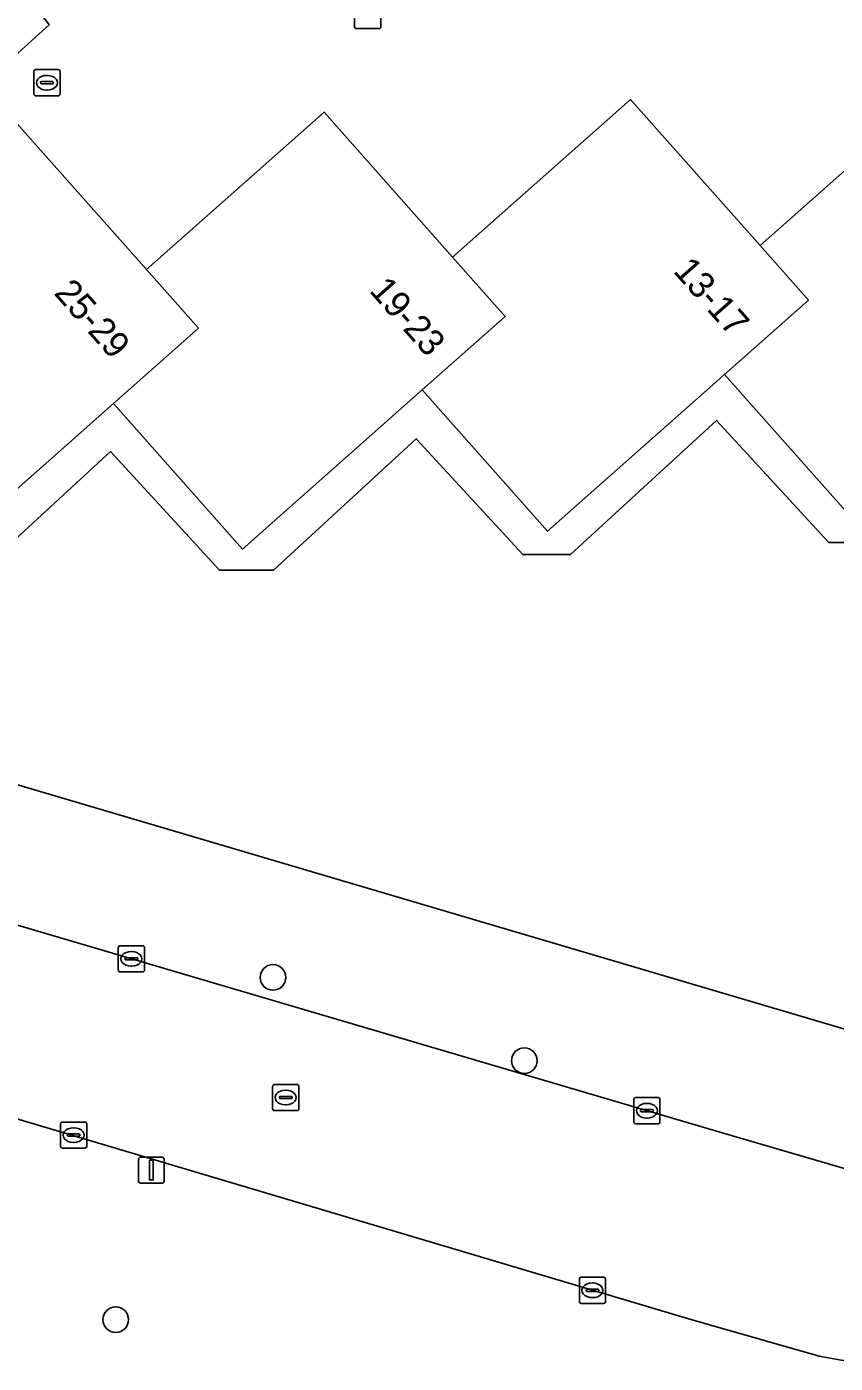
# Model space of a CAD drawing. Extents: x 160349 to 161355, y 381727 to 382854.
# Drawn here: x 160794 to 160824.9, y 381867.4 to 381918.5 of the extents above; entities that cross this region are included whole.
import ezdxf

# ---------------------------------------------------------------- set-up
doc = ezdxf.new("R2010")
doc.units = 0
for name, color, linetype in [('IMGEO_Berm_groen', 7, 'Continuous'), ('IMGEO_Boom', 7, 'Continuous'), ('IMGEO_Brandkraan', 7, 'Continuous'), ('IMGEO_Groenvoorziening', 7, 'Continuous'), ('IMGEO_Kolk', 7, 'Continuous'), ('IMGEO_Lichtmast', 7, 'Continuous'), ('IMGEO_Pand', 7, 'Continuous'), ('IMGEO_Pand_nummerreeks', 7, 'Continuous'), ('IMGEO_Rijbaan_lokaal_open', 7, 'Continuous'), ('IMGEO_Rioolput', 7, 'Continuous'), ('IMGEO_Voetpad_halfverhard', 7, 'Continuous'), ('IMGEO_Voetpad_open', 7, 'Continuous')]:
    doc.layers.add(name, color=color, linetype=linetype)

msp = doc.modelspace()

# ---------------------------------------------------------------- linework, layer by layer
at = {"layer": 'IMGEO_Berm_groen'}
msp.add_lwpolyline([(160824.304, 381867.688), (160819.275, 381869.125), (160815.643, 381870.203), (160710.934, 381901.384), (160677.174, 381911.473), (160673.041, 381902.206), (160697.175, 381891.554), (160719.115, 381882.137)], dxfattribs=at)
msp.add_arc((160826.897, 381879.851), 12.436, 257.9663, 319.7044, dxfattribs=at)
at = {"layer": 'IMGEO_Boom'}
for centre in [(160803.44, 381882.157), (160813.042, 381878.975), (160797.437, 381869.081)]:
    msp.add_circle(centre, 0.489, dxfattribs=at)
at = {"layer": 'IMGEO_Brandkraan'}
for p, q in [((160794.307, 381915.913), (160794.307, 381916.765)), ((160794.382, 381916.839), (160795.234, 381916.839)), ((160795.308, 381916.765), (160795.308, 381915.913)), ((160794.566, 381916.333), (160794.566, 381916.345)), ((160795.004, 381916.296), (160794.606, 381916.296)), ((160794.609, 381916.382), (160795.007, 381916.382)), ((160794.795, 381916.619), (160794.82, 381916.619)), ((160795.05, 381916.345), (160795.05, 381916.333)), ((160795.234, 381915.839), (160794.382, 381915.839)), ((160794.818, 381916.059), (160794.793, 381916.059))]:
    msp.add_line(p, q, dxfattribs=at)
for points in [[(160794.307, 381915.913), (160794.307, 381916.765)], [(160794.382, 381916.839), (160795.234, 381916.839)], [(160795.308, 381916.765), (160795.308, 381915.913)], [(160795.234, 381915.839), (160794.382, 381915.839)]]:
    msp.add_lwpolyline(points, dxfattribs=at)
for centre, radius, start, end in [((160794.384, 381916.763), 0.0765, 91.552, 178.448), ((160794.384, 381916.763), 0.0765, 91.552, 178.448), ((160795.232, 381916.763), 0.0765, 1.552, 88.448), ((160795.232, 381916.763), 0.0765, 1.552, 88.448), ((160794.606, 381916.342), 0.0403, 85.8775, 175.7526), ((160794.603, 381916.332), 0.0366, 178.938, 274.7102), ((160795.007, 381916.339), 0.043, 264.8664, 352.4533), ((160795.011, 381916.344), 0.0386, 1.7309, 96.639), ((160794.384, 381915.915), 0.0765, 181.552, 268.448), ((160794.384, 381915.915), 0.0765, 181.552, 268.448), ((160795.232, 381915.915), 0.0765, 271.552, 358.448), ((160795.232, 381915.915), 0.0765, 271.552, 358.448)]:
    msp.add_arc(centre, radius, start, end, dxfattribs=at)
for centre, major_axis, ratio, start_param, end_param in [((160794.794, 381916.339), (-0.387, 0.002), 0.722429, 4.712389, 7.853982), ((160794.819, 381916.339), (-0.39, 0.002), 0.717154, 1.570796, 4.712389)]:
    msp.add_ellipse(centre, major_axis=major_axis, ratio=ratio, start_param=start_param, end_param=end_param, dxfattribs=at)
at = {"layer": 'IMGEO_Groenvoorziening'}
for points in [[(160792.633, 381916.513), (160794.892, 381918.548), (160790.477, 381924.479), (160794.37, 381927.389), (160789.06, 381934.483)], [(160773.845, 381895.369), (160826.057, 381879.947), (160836.265, 381891.816), (160848.899, 381907.299), (160848.175, 381908.11), (160838.505, 381899.482), (160838.387, 381899.373), (160836.448, 381899.369), (160836.345, 381899.482), (160832.232, 381903.953), (160826.807, 381898.962), (160826.597, 381898.769), (160824.673, 381898.769), (160824.495, 381898.962), (160820.379, 381903.436), (160814.808, 381898.312), (160812.983, 381898.312), (160808.912, 381902.737), (160803.458, 381897.72), (160801.4, 381897.72), (160797.233, 381902.25), (160791.795, 381897.247)]]:
    msp.add_lwpolyline(points, dxfattribs=at)
at = {"layer": 'IMGEO_Kolk'}
for p, q in [((160806.56, 381918.479), (160806.56, 381919.331)), ((160807.561, 381919.331), (160807.561, 381918.479)), ((160807.487, 381918.405), (160806.635, 381918.405)), ((160797.535, 381882.441), (160797.535, 381883.293)), ((160797.61, 381883.367), (160798.462, 381883.367)), ((160798.023, 381883.147), (160798.048, 381883.147)), ((160798.536, 381883.293), (160798.536, 381882.441)), ((160797.794, 381882.861), (160797.794, 381882.873)), ((160798.232, 381882.824), (160797.834, 381882.824)), ((160797.837, 381882.91), (160798.235, 381882.91)), ((160798.046, 381882.587), (160798.021, 381882.587)), ((160798.278, 381882.873), (160798.278, 381882.861)), ((160798.462, 381882.367), (160797.61, 381882.367)), ((160817.219, 381876.638), (160817.219, 381877.49)), ((160817.294, 381877.564), (160818.146, 381877.564)), ((160818.22, 381877.49), (160818.22, 381876.638)), ((160817.478, 381877.058), (160817.478, 381877.07)), ((160817.916, 381877.021), (160817.518, 381877.021)), ((160817.521, 381877.107), (160817.919, 381877.107)), ((160817.707, 381877.344), (160817.732, 381877.344)), ((160817.962, 381877.07), (160817.962, 381877.058)), ((160795.329, 381875.706), (160795.329, 381876.558)), ((160795.404, 381876.632), (160796.256, 381876.632)), ((160795.817, 381876.412), (160795.842, 381876.412)), ((160796.33, 381876.558), (160796.33, 381875.706)), ((160818.146, 381876.564), (160817.294, 381876.564)), ((160817.73, 381876.784), (160817.705, 381876.784)), ((160795.588, 381876.126), (160795.588, 381876.138)), ((160796.026, 381876.089), (160795.628, 381876.089)), ((160795.631, 381876.175), (160796.029, 381876.175)), ((160796.072, 381876.138), (160796.072, 381876.126)), ((160796.256, 381875.632), (160795.404, 381875.632)), ((160795.84, 381875.852), (160795.815, 381875.852)), ((160815.142, 381869.776), (160815.142, 381870.628)), ((160815.217, 381870.702), (160816.069, 381870.702)), ((160815.63, 381870.482), (160815.655, 381870.482)), ((160816.143, 381870.628), (160816.143, 381869.776)), ((160815.401, 381870.196), (160815.401, 381870.208)), ((160815.839, 381870.159), (160815.441, 381870.159)), ((160815.444, 381870.245), (160815.842, 381870.245)), ((160815.653, 381869.922), (160815.628, 381869.922)), ((160815.885, 381870.208), (160815.885, 381870.196)), ((160816.069, 381869.702), (160815.217, 381869.702))]:
    msp.add_line(p, q, dxfattribs=at)
for points in [[(160806.56, 381918.479), (160806.56, 381919.331)], [(160807.561, 381919.331), (160807.561, 381918.479)], [(160807.487, 381918.405), (160806.635, 381918.405)], [(160797.535, 381882.441), (160797.535, 381883.293)], [(160797.61, 381883.367), (160798.462, 381883.367)], [(160798.536, 381883.293), (160798.536, 381882.441)], [(160798.462, 381882.367), (160797.61, 381882.367)], [(160817.219, 381876.638), (160817.219, 381877.49)], [(160817.294, 381877.564), (160818.146, 381877.564)], [(160818.22, 381877.49), (160818.22, 381876.638)], [(160795.329, 381875.706), (160795.329, 381876.558)], [(160795.404, 381876.632), (160796.256, 381876.632)], [(160796.33, 381876.558), (160796.33, 381875.706)], [(160818.146, 381876.564), (160817.294, 381876.564)], [(160796.256, 381875.632), (160795.404, 381875.632)], [(160815.142, 381869.776), (160815.142, 381870.628)], [(160815.217, 381870.702), (160816.069, 381870.702)], [(160816.143, 381870.628), (160816.143, 381869.776)], [(160816.069, 381869.702), (160815.217, 381869.702)]]:
    msp.add_lwpolyline(points, dxfattribs=at)
for centre, radius, start, end in [((160806.637, 381918.481), 0.0765, 181.552, 268.448), ((160806.637, 381918.481), 0.0765, 181.552, 268.448), ((160807.485, 381918.481), 0.0765, 271.552, 358.448), ((160807.485, 381918.481), 0.0765, 271.552, 358.448), ((160797.612, 381883.291), 0.0765, 91.552, 178.448), ((160797.612, 381883.291), 0.0765, 91.552, 178.448), ((160798.46, 381883.291), 0.0765, 1.552, 88.448), ((160798.46, 381883.291), 0.0765, 1.552, 88.448), ((160797.834, 381882.87), 0.0403, 85.8775, 175.7526), ((160797.831, 381882.86), 0.0366, 178.938, 274.7102), ((160798.235, 381882.867), 0.043, 264.8664, 352.4533), ((160798.239, 381882.872), 0.0386, 1.7309, 96.639), ((160797.612, 381882.443), 0.0765, 181.552, 268.448), ((160797.612, 381882.443), 0.0765, 181.552, 268.448), ((160798.46, 381882.443), 0.0765, 271.552, 358.448), ((160798.46, 381882.443), 0.0765, 271.552, 358.448), ((160817.296, 381877.488), 0.0765, 91.552, 178.448), ((160817.296, 381877.488), 0.0765, 91.552, 178.448), ((160818.144, 381877.488), 0.0765, 1.552, 88.448), ((160818.144, 381877.488), 0.0765, 1.552, 88.448), ((160817.518, 381877.067), 0.0403, 85.8775, 175.7526), ((160817.515, 381877.057), 0.0366, 178.938, 274.7102), ((160817.919, 381877.064), 0.043, 264.8664, 352.4533), ((160817.923, 381877.069), 0.0386, 1.7309, 96.639), ((160795.406, 381876.556), 0.0765, 91.552, 178.448), ((160795.406, 381876.556), 0.0765, 91.552, 178.448), ((160796.254, 381876.556), 0.0765, 1.552, 88.448), ((160796.254, 381876.556), 0.0765, 1.552, 88.448), ((160817.296, 381876.64), 0.0765, 181.552, 268.448), ((160817.296, 381876.64), 0.0765, 181.552, 268.448), ((160818.144, 381876.64), 0.0765, 271.552, 358.448), ((160818.144, 381876.64), 0.0765, 271.552, 358.448), ((160795.628, 381876.135), 0.0403, 85.8775, 175.7526), ((160795.625, 381876.125), 0.0366, 178.938, 274.7102), ((160796.029, 381876.132), 0.043, 264.8664, 352.4533), ((160796.033, 381876.137), 0.0386, 1.7309, 96.639), ((160795.406, 381875.708), 0.0765, 181.552, 268.448), ((160795.406, 381875.708), 0.0765, 181.552, 268.448), ((160796.254, 381875.708), 0.0765, 271.552, 358.448), ((160796.254, 381875.708), 0.0765, 271.552, 358.448), ((160815.219, 381870.626), 0.0765, 91.552, 178.448), ((160815.219, 381870.626), 0.0765, 91.552, 178.448), ((160816.067, 381870.626), 0.0765, 1.552, 88.448), ((160816.067, 381870.626), 0.0765, 1.552, 88.448), ((160815.219, 381869.778), 0.0765, 181.552, 268.448), ((160815.219, 381869.778), 0.0765, 181.552, 268.448), ((160815.441, 381870.205), 0.0403, 85.8775, 175.7526), ((160815.438, 381870.195), 0.0366, 178.938, 274.7102), ((160815.842, 381870.202), 0.043, 264.8664, 352.4533), ((160815.846, 381870.207), 0.0386, 1.7309, 96.639), ((160816.067, 381869.778), 0.0765, 271.552, 358.448), ((160816.067, 381869.778), 0.0765, 271.552, 358.448)]:
    msp.add_arc(centre, radius, start, end, dxfattribs=at)
for centre, major_axis, ratio, start_param, end_param in [((160798.022, 381882.867), (-0.387, 0.002), 0.722429, 4.712389, 7.853982), ((160798.047, 381882.867), (-0.39, 0.002), 0.717154, 1.570796, 4.712389), ((160817.706, 381877.064), (-0.387, 0.002), 0.722429, 4.712389, 7.853982), ((160817.731, 381877.064), (-0.39, 0.002), 0.717154, 1.570796, 4.712389), ((160795.816, 381876.132), (-0.387, 0.002), 0.722429, 4.712389, 7.853982), ((160795.841, 381876.132), (-0.39, 0.002), 0.717154, 1.570796, 4.712389), ((160815.629, 381870.202), (-0.387, 0.002), 0.722429, 4.712389, 7.853982), ((160815.654, 381870.202), (-0.39, 0.002), 0.717154, 1.570796, 4.712389)]:
    msp.add_ellipse(centre, major_axis=major_axis, ratio=ratio, start_param=start_param, end_param=end_param, dxfattribs=at)
at = {"layer": 'IMGEO_Lichtmast'}
for p, q in [((160798.299, 381874.394), (160798.299, 381875.194)), ((160798.299, 381875.194), (160798.299, 381874.394)), ((160798.399, 381875.294), (160799.189, 381875.294)), ((160799.189, 381875.294), (160798.399, 381875.294)), ((160799.289, 381875.194), (160799.289, 381874.394)), ((160799.289, 381874.394), (160799.289, 381875.194)), ((160799.189, 381874.294), (160798.399, 381874.294)), ((160798.399, 381874.294), (160799.189, 381874.294))]:
    msp.add_line(p, q, dxfattribs=at)
msp.add_lwpolyline([(160798.719, 381875.169), (160798.869, 381875.169), (160798.869, 381874.419), (160798.719, 381874.419), (160798.719, 381875.169)], dxfattribs=at)
for centre, start, end in [((160798.399, 381875.194), 90, 180), ((160798.399, 381875.194), 90, 180), ((160799.189, 381875.194), 0, 90), ((160799.189, 381875.194), 360, 90), ((160798.399, 381874.394), 180, 270), ((160798.399, 381874.394), 180, 270), ((160799.189, 381874.394), 270, 0), ((160799.189, 381874.394), 270, 0)]:
    msp.add_arc(centre, 0.1, start, end, dxfattribs=at)
at = {"layer": 'IMGEO_Pand'}
for points in [[(160822.045, 381910.121), (160823.891, 381908.037), (160820.686, 381905.198), (160825.625, 381899.622), (160832.495, 381905.707), (160835.617, 381908.472), (160833.696, 381910.641), (160828.833, 381916.132)], [(160798.607, 381909.202), (160800.593, 381906.96), (160797.346, 381904.085), (160802.276, 381898.519), (160809.142, 381904.6), (160812.311, 381907.407), (160810.299, 381909.679), (160805.397, 381915.215)], [(160809.142, 381904.6), (160813.92, 381899.205), (160820.686, 381905.198), (160823.891, 381908.037), (160822.045, 381910.121), (160817.101, 381915.703), (160810.299, 381909.679), (160812.311, 381907.407)], [(160798.607, 381909.202), (160793.675, 381914.77), (160786.891, 381908.762), (160786.177, 381908.13), (160786.618, 381907.631), (160786.99, 381907.961), (160787.432, 381907.462), (160788.32, 381906.46), (160785.459, 381903.926), (160790.605, 381898.115), (160797.346, 381904.085), (160800.593, 381906.96)]]:
    msp.add_lwpolyline(points, close=True, dxfattribs=at)
at = {"layer": 'IMGEO_Rijbaan_lokaal_open'}
for points in [[(160703.301, 381910.962), (160691.804, 381914.329), (160679.993, 381917.834), (160677.174, 381911.473), (160710.934, 381901.384), (160815.643, 381870.203), (160819.275, 381869.125), (160824.304, 381867.688)], [(160826.955, 381874.36), (160820.691, 381876.187), (160744.941, 381898.519), (160740.094, 381899.948), (160729.348, 381903.194), (160724.219, 381904.806), (160713.383, 381907.976), (160703.301, 381910.962)]]:
    msp.add_lwpolyline(points, dxfattribs=at)
msp.add_arc((160826.897, 381879.851), 12.436, 257.9663, 319.7044, dxfattribs=at)
at = {"layer": 'IMGEO_Rioolput'}
for p, q in [((160803.429, 381877.142), (160803.429, 381877.994)), ((160803.504, 381878.068), (160804.356, 381878.068)), ((160804.43, 381877.994), (160804.43, 381877.142)), ((160803.688, 381877.562), (160803.688, 381877.574)), ((160804.126, 381877.525), (160803.728, 381877.525)), ((160803.731, 381877.611), (160804.129, 381877.611)), ((160803.917, 381877.848), (160803.942, 381877.848)), ((160804.172, 381877.574), (160804.172, 381877.562)), ((160804.356, 381877.068), (160803.504, 381877.068)), ((160803.94, 381877.288), (160803.915, 381877.288))]:
    msp.add_line(p, q, dxfattribs=at)
for points in [[(160803.429, 381877.142), (160803.429, 381877.994)], [(160803.504, 381878.068), (160804.356, 381878.068)], [(160804.43, 381877.994), (160804.43, 381877.142)], [(160804.356, 381877.068), (160803.504, 381877.068)]]:
    msp.add_lwpolyline(points, dxfattribs=at)
for centre, radius, start, end in [((160803.506, 381877.992), 0.0765, 91.552, 178.448), ((160803.506, 381877.992), 0.0765, 91.552, 178.448), ((160804.354, 381877.992), 0.0765, 1.552, 88.448), ((160804.354, 381877.992), 0.0765, 1.552, 88.448), ((160803.728, 381877.571), 0.0403, 85.8775, 175.7526), ((160803.725, 381877.561), 0.0366, 178.938, 274.7102), ((160804.129, 381877.568), 0.043, 264.8664, 352.4533), ((160804.133, 381877.573), 0.0386, 1.7309, 96.639), ((160803.506, 381877.144), 0.0765, 181.552, 268.448), ((160803.506, 381877.144), 0.0765, 181.552, 268.448), ((160804.354, 381877.144), 0.0765, 271.552, 358.448), ((160804.354, 381877.144), 0.0765, 271.552, 358.448)]:
    msp.add_arc(centre, radius, start, end, dxfattribs=at)
for centre, major_axis, ratio, start_param, end_param in [((160803.916, 381877.568), (-0.387, 0.002), 0.722429, 4.712389, 7.853982), ((160803.941, 381877.568), (-0.39, 0.002), 0.717154, 1.570796, 4.712389)]:
    msp.add_ellipse(centre, major_axis=major_axis, ratio=ratio, start_param=start_param, end_param=end_param, dxfattribs=at)
at = {"layer": 'IMGEO_Voetpad_halfverhard'}
for points in [[(160825.625, 381899.622), (160820.686, 381905.198), (160813.92, 381899.205), (160809.142, 381904.6), (160802.276, 381898.519), (160797.346, 381904.085), (160790.605, 381898.115)], [(160791.795, 381897.247), (160797.233, 381902.25), (160801.4, 381897.72), (160803.458, 381897.72), (160808.912, 381902.737), (160812.983, 381898.312), (160814.808, 381898.312), (160820.379, 381903.436), (160824.495, 381898.962), (160824.673, 381898.769), (160826.597, 381898.769)]]:
    msp.add_lwpolyline(points, dxfattribs=at)
at = {"layer": 'IMGEO_Voetpad_open'}
for points in [[(160789.06, 381934.483), (160794.37, 381927.389), (160790.477, 381924.479), (160794.892, 381918.548), (160792.633, 381916.513)], [(160793.675, 381914.77), (160798.607, 381909.202), (160805.397, 381915.215), (160810.299, 381909.679), (160817.101, 381915.703), (160822.045, 381910.121), (160828.833, 381916.132), (160833.696, 381910.641), (160840.55, 381916.712), (160847.359, 381909.025), (160848.175, 381908.11), (160848.899, 381907.299), (160854.514, 381914.18), (160835.192, 381923.816)], [(160676.897, 381918.763), (160677.146, 381918.679), (160679.993, 381917.834), (160691.804, 381914.329), (160703.301, 381910.962), (160713.383, 381907.976), (160724.219, 381904.806), (160729.348, 381903.194), (160740.094, 381899.948), (160744.941, 381898.519), (160820.691, 381876.187), (160826.955, 381874.36)], [(160827.927, 381874.212), (160829.162, 381878.717), (160826.057, 381879.947), (160773.845, 381895.369), (160771.213, 381896.146), (160770.721, 381896.291), (160746.482, 381903.49)]]:
    msp.add_lwpolyline(points, dxfattribs=at)

# ---------------------------------------------------------------- texts
at = {"layer": 'IMGEO_Pand_nummerreeks'}
for s, rotation, p in [('13-17', 311.5167, (160818.692, 381909.125)), ('25-29', 311.5163, (160795.045, 381908.284)), ('19-23', 311.5167, (160807.086, 381908.376))]:
    msp.add_text(s, height=1, rotation=rotation, dxfattribs=at).set_placement(p)

doc.saveas('drawing.dxf')
